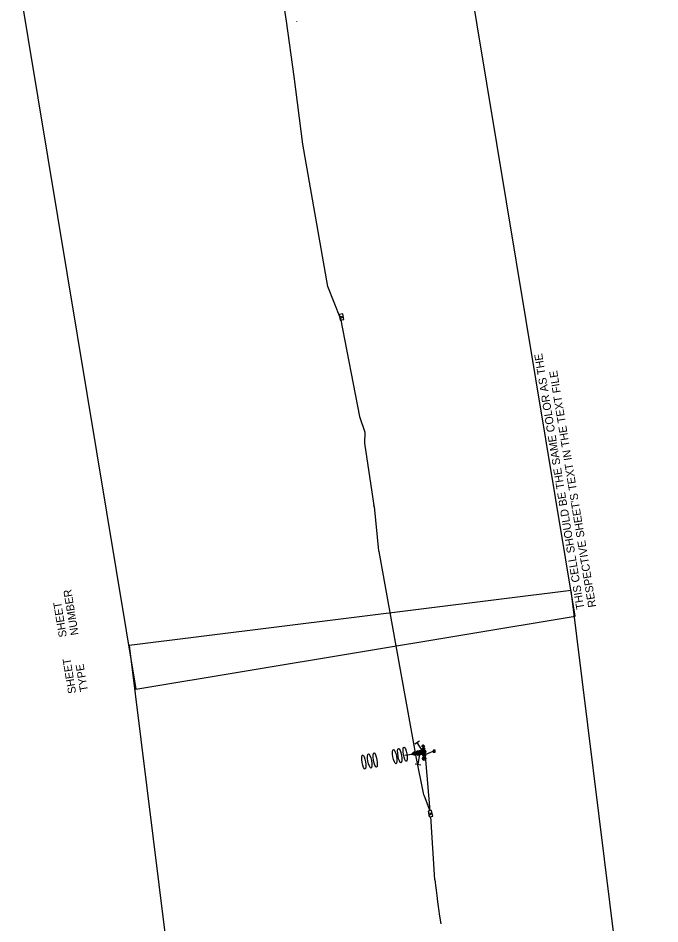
# Model space of a CAD drawing. Extents: x 601462 to 605493, y 331960 to 402715.
# Drawn here: x 603985 to 605389, y 335860 to 337841 of the extents above; entities that cross this region are included whole.
import ezdxf

# ---------------------------------------------------------------- set-up
doc = ezdxf.new("R2010")
doc.units = 0
for name, color, linetype in [('P_FTMS', 7, 'Continuous'), ('P_FTMSConduit', 7, 'Continuous'), ('P_MISC_TXT_2A (Construction)', 7, 'Continuous'), ('P_MISC_TXT_2B (Construction)', 7, 'Continuous')]:
    doc.layers.add(name, color=color, linetype=linetype)

# ---------------------------------------------------------------- blocks, each defined once
blk = doc.blocks.new('FTMS_FCV')
at = {"layer": 'P_FTMS'}
blk.add_line((13, 16), (1, -22), dxfattribs=at)
blk.add_lwpolyline([(39, 24), (-39, 24), (-39, -24), (39, -24)], close=True, dxfattribs=at)
blk.add_lwpolyline([(-12, 16), (1, -22)], dxfattribs=at)
blk = doc.blocks.new('FMD')
at = {"layer": 'P_FTMS'}
for p, q in [((17, 18), (-17, 18)), ((-16, 16), (-16, 18)), ((16, 16), (-16, 16)), ((-15, 15), (-15, 20)), ((15, 19), (-15, 19)), ((15, 15), (-15, 15)), ((14, 20), (-14, 20)), ((13, 22), (-13, 22)), ((-13, 13), (-13, 21)), ((13, 13), (-13, 13)), ((-12, 12), (-12, 23)), ((12, 12), (-12, 12)), ((11, 23), (-11, 23)), ((10, 25), (-10, 25)), ((-10, 10), (-10, 24)), ((10, 10), (-10, 10)), ((-9, 9), (-9, 26)), ((9, 9), (-9, 9)), ((8, 26), (-8, 26)), ((7, 28), (-7, 28)), ((-7, 7), (-7, 27)), ((7, 7), (-7, 7)), ((-6, 6), (-6, 29)), ((6, 6), (-6, 6)), ((5, 29), (-5, 29)), ((4, 31), (-4, 31)), ((-4, 4), (-4, 30)), ((4, 4), (-4, 4)), ((-3, 3), (-3, 32)), ((3, 3), (-3, 3)), ((2, 32), (-2, 32)), ((1, 34), (-1, 34)), ((-1, 1), (-1, 33)), ((1, 1), (-1, 1)), ((0, 0), (0, 34)), ((1, 1), (1, 33)), ((3, 3), (3, 32)), ((4, 4), (4, 30)), ((6, 6), (6, 29)), ((7, 7), (7, 27)), ((9, 9), (9, 26)), ((10, 10), (10, 24)), ((12, 12), (12, 23)), ((13, 13), (13, 21)), ((15, 15), (15, 20)), ((16, 16), (16, 18))]:
    blk.add_line(p, q, dxfattribs=at)
blk.add_lwpolyline([(-17, 17), (0, 34), (17, 17), (0, 0)], close=True, dxfattribs=at)
blk = doc.blocks.new('FMB')
at = {"layer": 'P_FTMS'}
for p, q in [((24, -24), (-24, 24)), ((-24, -24), (24, 24))]:
    blk.add_line(p, q, dxfattribs=at)
blk.add_lwpolyline([(24, -24), (24, 24), (-24, 24), (-24, -24)], close=True, dxfattribs=at)
blk = doc.blocks.new('_U256')
at = {"layer": 'P_FTMS'}
for points in [[(-15, -7), (7, -15), (0, 0)], [(15, 7), (-7, 15), (0, 0)]]:
    blk.add_lwpolyline(points, close=True, dxfattribs=at)
at = {"layer": 'P_FTMS', "xscale": 0.4713263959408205, "yscale": 0.4713263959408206, "rotation": 70.39802054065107}
blk.add_blockref('FMB', (0, 0), dxfattribs=at)
blk = doc.blocks.new('FTMS')
at = {"layer": 'P_FTMS'}
for p, q in [((-23, 0), (26, 0)), ((0, 24), (0, -24))]:
    blk.add_line(p, q, dxfattribs=at)
blk.add_lwpolyline([(26, -24), (26, 24), (-23, 24), (-23, -24)], close=True, dxfattribs=at)
blk = doc.blocks.new('FTMS_FERA')
at = {"layer": 'P_FTMS'}
for p, q in [((-65, 37), (-65, -37)), ((65, 0), (-65, 0))]:
    blk.add_line(p, q, dxfattribs=at)

msp = doc.modelspace()

# ---------------------------------------------------------------- linework, layer by layer
at = {"layer": 'P_FTMS'}
for p, q in [((604868.9, 336236), (604871.8, 336240)), ((604868.9, 336236.3), (604871.4, 336239.9)), ((604869, 336235.3), (604872.5, 336240.1)), ((604869, 336235.6), (604872.2, 336240.1)), ((604869.1, 336235), (604872.8, 336240.2)), ((604869.2, 336234.7), (604873.1, 336240.2)), ((604869.3, 336234.4), (604873.4, 336240.1)), ((604869.5, 336234.2), (604873.6, 336240.1)), ((604869.6, 336234), (604873.9, 336240)), ((604869.7, 336233.8), (604874.1, 336240)), ((604869.9, 336233.6), (604874.4, 336239.9)), ((604876.9, 336236), (604871.4, 336239.9)), ((604876.9, 336236.3), (604871.7, 336240)), ((604876.9, 336236.6), (604872, 336240.1)), ((604876.8, 336236.9), (604872.3, 336240.1)), ((604876.7, 336237.3), (604872.7, 336240.2)), ((604876.6, 336237.7), (604873.1, 336240.2)), ((604876.4, 336238.1), (604873.6, 336240.1)), ((604876, 336238.7), (604874.2, 336240)), ((604831.4, 336229), (604846.4, 336231.6)), ((604846.4, 336231.6), (604846.4, 336231.6)), ((604846.6, 336231.5), (604847.1, 336232.2)), ((604847.3, 336231.3), (604846.6, 336231.8)), ((604848.2, 336231), (604846.8, 336231.9)), ((604846.9, 336231.4), (604847.8, 336232.8)), ((604849, 336230.6), (604847, 336232.1)), ((604847.1, 336231.4), (604848.6, 336233.4)), ((604849.9, 336230.3), (604847.2, 336232.3)), ((604847.3, 336231.3), (604849.3, 336234)), ((604850.8, 336230), (604847.4, 336232.4)), ((604847.6, 336231.2), (604850, 336234.6)), ((604851.6, 336229.7), (604847.6, 336232.6)), ((604847.8, 336231.1), (604850.7, 336235.2)), ((604852.5, 336229.4), (604847.8, 336232.7)), ((604853.4, 336229), (604847.9, 336232.9)), ((604848, 336231), (604851.4, 336235.8)), ((604853.9, 336229), (604848.1, 336233)), ((604848.3, 336230.9), (604852.1, 336236.4)), ((604853.8, 336229.3), (604848.3, 336233.2)), ((604848.5, 336230.8), (604852.6, 336236.6)), ((604853.7, 336229.7), (604848.5, 336233.4)), ((604848.7, 336230.8), (604852.6, 336236.2)), ((604853.7, 336230), (604848.7, 336233.5)), ((604853.6, 336230.3), (604848.9, 336233.7)), ((604849, 336230.7), (604852.7, 336235.9)), ((604853.6, 336230.7), (604849.1, 336233.8)), ((604849.2, 336230.6), (604852.7, 336235.6)), ((604853.5, 336231), (604849.3, 336234)), ((604849.4, 336230.5), (604852.8, 336235.2)), ((604853.5, 336231.3), (604849.5, 336234.2)), ((604849.7, 336230.4), (604852.8, 336234.9)), ((604853.4, 336231.7), (604849.7, 336234.3)), ((604849.9, 336230.3), (604852.9, 336234.6)), ((604853.3, 336232), (604849.9, 336234.5)), ((604853.3, 336232.3), (604850, 336234.6)), ((604850.1, 336230.2), (604853, 336234.2)), ((604853.2, 336232.7), (604850.2, 336234.8)), ((604853.2, 336233), (604850.4, 336235)), ((604850.4, 336230.2), (604853, 336233.9)), ((604853.1, 336233.3), (604850.6, 336235.1)), ((604850.6, 336230.1), (604853.1, 336233.6)), ((604853.1, 336233.7), (604850.8, 336235.3)), ((604850.8, 336230), (604853.1, 336233.2)), ((604853, 336234), (604851, 336235.4)), ((604851.1, 336229.9), (604853.2, 336232.9)), ((604852.9, 336234.3), (604851.2, 336235.6)), ((604851.3, 336229.8), (604853.2, 336232.5)), ((604852.9, 336234.7), (604851.4, 336235.7)), ((604851.5, 336229.7), (604853.3, 336232.2)), ((604852.8, 336235), (604851.6, 336235.9)), ((604852.8, 336235.4), (604851.8, 336236.1)), ((604851.8, 336229.6), (604853.4, 336231.9)), ((604852.7, 336235.7), (604852, 336236.2)), ((604852, 336229.5), (604853.4, 336231.5)), ((604852.7, 336236), (604852.1, 336236.4)), ((604852.2, 336229.5), (604853.5, 336231.2)), ((604852.6, 336236.4), (604852.3, 336236.5)), ((604852.5, 336236.7), (604852.5, 336236.7)), ((604852.5, 336229.4), (604853.5, 336230.9)), ((604852.7, 336229.3), (604853.6, 336230.5)), ((604852.9, 336229.2), (604853.7, 336230.2)), ((604857.1, 336233.5), (604853.2, 336232.8)), ((604853.2, 336229.1), (604853.7, 336229.9)), ((604853.4, 336229), (604853.8, 336229.5)), ((604853.6, 336228.9), (604853.8, 336229.2)), ((604853.9, 336228.9), (604853.9, 336228.9)), ((604856.5, 336237.2), (604856.7, 336237.4)), ((604865.5, 336230.9), (604856.5, 336237.2)), ((604856.6, 336236.6), (604857.3, 336237.6)), ((604856.6, 336236.9), (604857, 336237.5)), ((604865.9, 336230.9), (604856.6, 336237.4)), ((604865.2, 336230.8), (604856.6, 336236.9)), ((604864.8, 336230.7), (604856.6, 336236.6)), ((604856.7, 336235.9), (604858, 336237.7)), ((604856.7, 336236.2), (604857.7, 336237.6)), ((604864.5, 336230.7), (604856.7, 336236.2)), ((604864.2, 336230.6), (604856.7, 336235.9)), ((604856.8, 336235.2), (604858.7, 336237.8)), ((604856.8, 336235.6), (604858.3, 336237.7)), ((604863.8, 336230.6), (604856.8, 336235.6)), ((604863.5, 336230.5), (604856.8, 336235.2)), ((604856.9, 336234.9), (604859, 336237.9)), ((604863.2, 336230.4), (604856.9, 336234.9)), ((604857, 336234.2), (604859.7, 336238)), ((604857, 336234.5), (604859.3, 336237.9)), ((604866.2, 336231), (604857, 336237.5)), ((604862.8, 336230.4), (604857, 336234.5)), ((604862.5, 336230.3), (604857, 336234.2)), ((604857.1, 336233.5), (604860.3, 336238.1)), ((604857.1, 336233.9), (604860, 336238)), ((604862.2, 336230.3), (604857.1, 336233.9)), ((604861.8, 336230.2), (604857.1, 336233.5)), ((604857.2, 336233.2), (604860.7, 336238.1)), ((604861.5, 336230.2), (604857.2, 336233.2)), ((604857.3, 336232.5), (604861.3, 336238.3)), ((604857.3, 336232.9), (604861, 336238.2)), ((604866.5, 336231), (604857.3, 336237.6)), ((604861.2, 336230.1), (604857.3, 336232.9)), ((604860.8, 336230), (604857.3, 336232.5)), ((604857.4, 336231.9), (604862, 336238.4)), ((604857.4, 336232.2), (604861.7, 336238.3)), ((604860.5, 336230), (604857.4, 336232.2)), ((604860.2, 336229.9), (604857.4, 336231.9)), ((604857.5, 336231.2), (604862.7, 336238.5)), ((604857.5, 336231.5), (604862.4, 336238.4)), ((604859.8, 336229.9), (604857.5, 336231.5)), ((604859.5, 336229.8), (604857.5, 336231.2)), ((604857.6, 336230.9), (604863, 336238.5)), ((604866.9, 336231.1), (604857.6, 336237.6)), ((604859.2, 336229.8), (604857.6, 336230.9)), ((604857.7, 336230.2), (604863.7, 336238.7)), ((604857.7, 336230.5), (604863.4, 336238.6)), ((604858.8, 336229.7), (604857.7, 336230.5)), ((604858.5, 336229.6), (604857.7, 336230.2)), ((604857.8, 336229.5), (604864.4, 336238.8)), ((604857.8, 336229.9), (604864, 336238.7)), ((604858.2, 336229.6), (604857.8, 336229.9)), ((604867.2, 336231.1), (604858, 336237.7)), ((604858.2, 336229.6), (604864.7, 336238.8)), ((604867.5, 336231.2), (604858.3, 336237.7)), ((604858.5, 336229.6), (604865, 336238.9)), ((604867.9, 336231.3), (604858.6, 336237.8)), ((604858.8, 336229.7), (604865.4, 336238.9)), ((604868.2, 336231.3), (604859, 336237.8)), ((604859.2, 336229.8), (604865.7, 336239)), ((604868.5, 336231.4), (604859.3, 336237.9)), ((604859.5, 336229.8), (604866, 336239.1)), ((604868.9, 336231.4), (604859.6, 336238)), ((604859.8, 336229.9), (604866.4, 336239.1)), ((604869.2, 336231.5), (604860, 336238)), ((604860.2, 336229.9), (604866.7, 336239.2)), ((604869.5, 336231.5), (604860.3, 336238.1)), ((604860.5, 336230), (604867, 336239.2)), ((604869.6, 336231.8), (604860.6, 336238.1)), ((604860.8, 336230), (604867.4, 336239.3)), ((604869.6, 336232.1), (604861, 336238.2)), ((604861.2, 336230.1), (604867.7, 336239.3)), ((604869.5, 336232.4), (604861.3, 336238.2)), ((604861.5, 336230.2), (604868, 336239.4)), ((604869.4, 336232.8), (604861.6, 336238.3)), ((604861.8, 336230.2), (604868.3, 336239.4)), ((604869.4, 336233.1), (604862, 336238.4)), ((604862.2, 336230.3), (604868.4, 336239)), ((604869.3, 336233.4), (604862.3, 336238.4)), ((604862.5, 336230.3), (604868.4, 336238.7)), ((604869.3, 336233.8), (604862.6, 336238.5)), ((604862.8, 336230.4), (604868.5, 336238.4)), ((604869.2, 336234.1), (604863, 336238.5)), ((604863.2, 336230.4), (604868.5, 336238)), ((604869.2, 336234.5), (604863.3, 336238.6)), ((604863.5, 336230.5), (604868.6, 336237.7)), ((604869.1, 336234.8), (604863.6, 336238.6)), ((604863.8, 336230.6), (604868.7, 336237.4)), ((604869, 336235.1), (604864, 336238.7)), ((604864.2, 336230.6), (604868.7, 336237)), ((604869, 336235.5), (604864.3, 336238.8)), ((604864.3, 336234.7), (604864.5, 336234.7)), ((604864.3, 336234.7), (604864.3, 336234.7)), ((604864.5, 336230.7), (604868.8, 336236.7)), ((604868.9, 336235.8), (604864.6, 336238.8)), ((604864.8, 336230.7), (604868.8, 336236.4)), ((604868.9, 336236.1), (604865, 336238.9)), ((604865.2, 336230.8), (604868.9, 336236)), ((604868.8, 336236.5), (604865.3, 336238.9)), ((604865.5, 336230.9), (604868.9, 336235.7)), ((604868.8, 336236.8), (604865.6, 336239)), ((604865.9, 336230.9), (604869, 336235.4)), ((604868.7, 336237.1), (604866, 336239)), ((604866.2, 336231), (604869.1, 336235)), ((604868.6, 336237.5), (604866.3, 336239.1)), ((604866.5, 336231), (604869.1, 336234.7)), ((604868.6, 336237.8), (604866.7, 336239.2)), ((604866.9, 336231.1), (604869.2, 336234.4)), ((604868.5, 336238.1), (604867, 336239.2)), ((604867.2, 336231.1), (604869.2, 336234)), ((604868.5, 336238.5), (604867.3, 336239.3)), ((604867.5, 336231.2), (604869.3, 336233.7)), ((604868.4, 336238.8), (604867.7, 336239.3)), ((604867.9, 336231.3), (604869.3, 336233.4)), ((604868.4, 336239.1), (604868, 336239.4)), ((604868.2, 336231.3), (604869.4, 336233)), ((604868.5, 336231.4), (604869.5, 336232.7)), ((604874.4, 336232.5), (604868.9, 336236.4)), ((604874.1, 336232.4), (604868.9, 336236.1)), ((604873.8, 336232.3), (604868.9, 336235.8)), ((604868.9, 336231.4), (604869.5, 336232.3)), ((604869, 336236.9), (604871, 336239.7)), ((604875.1, 336232.8), (604869, 336237.2)), ((604874.9, 336232.7), (604869, 336236.9)), ((604874.7, 336232.6), (604869, 336236.6)), ((604873.5, 336232.2), (604869, 336235.4)), ((604875.3, 336233), (604869.1, 336237.4)), ((604873.2, 336232.2), (604869.1, 336235.1)), ((604869.2, 336237.5), (604870.4, 336239.3)), ((604875.5, 336233.2), (604869.2, 336237.6)), ((604872.7, 336232.2), (604869.2, 336234.7)), ((604869.2, 336231.5), (604869.6, 336232)), ((604875.7, 336233.3), (604869.3, 336237.9)), ((604875.9, 336233.5), (604869.4, 336238.1)), ((604872.2, 336232.3), (604869.4, 336234.2)), ((604876, 336233.7), (604869.5, 336238.3)), ((604869.5, 336231.5), (604869.6, 336231.7)), ((604876.2, 336233.9), (604869.7, 336238.5)), ((604876.3, 336234.1), (604869.8, 336238.7)), ((604871.6, 336232.4), (604869.8, 336233.7)), ((604876.4, 336234.3), (604870, 336238.9)), ((604870.1, 336233.4), (604874.6, 336239.8)), ((604876.5, 336234.5), (604870.1, 336239)), ((604870.2, 336233.2), (604874.8, 336239.7)), ((604876.6, 336234.7), (604870.3, 336239.2)), ((604870.4, 336233.1), (604875, 336239.6)), ((604876.7, 336235), (604870.5, 336239.4)), ((604870.6, 336232.9), (604875.2, 336239.4)), ((604876.8, 336235.2), (604870.7, 336239.5)), ((604870.8, 336232.8), (604875.4, 336239.3)), ((604876.8, 336235.5), (604870.9, 336239.6)), ((604871, 336232.7), (604875.6, 336239.1)), ((604876.9, 336235.7), (604871.2, 336239.8)), ((604871.2, 336232.6), (604875.8, 336239)), ((604871.5, 336232.5), (604875.9, 336238.8)), ((604871.7, 336232.4), (604876.1, 336238.6)), ((604871.9, 336232.3), (604876.2, 336238.4)), ((604872.2, 336232.3), (604876.4, 336238.2)), ((604872.5, 336232.2), (604876.5, 336237.9)), ((604872.7, 336232.2), (604876.6, 336237.7)), ((604873, 336232.2), (604876.7, 336237.4)), ((604873.3, 336232.2), (604876.8, 336237.1)), ((604873.7, 336232.3), (604876.9, 336236.8)), ((604874, 336232.3), (604876.9, 336236.4)), ((604874.4, 336232.5), (604876.9, 336236)), ((604874.9, 336232.7), (604876.9, 336235.5)), ((604875.4, 336233.1), (604876.7, 336234.8))]:
    msp.add_line(p, q, dxfattribs=at)
for points in [[(604853.9, 336228.9), (604852.5, 336236.7), (604846.4, 336231.6)], [(604868.3, 336239.4), (604856.5, 336237.4), (604857.8, 336229.5), (604869.7, 336231.6)]]:
    msp.add_lwpolyline(points, close=True, dxfattribs=at)
for centre, radius in [((604872.9, 336236.2), 4), ((604873.4, 336221.6), 3.75)]:
    msp.add_circle(centre, radius, dxfattribs=at)
for centre, start, end in [((604873.5, 336226.1), 216.2095, 322.4651), ((604873.4, 336217.1), 36.2095, 142.4651)]:
    msp.add_arc(centre, 3.75, start, end, dxfattribs=at)
for centre in [(604808.8, 336226.1), (604819.9, 336228), (604831.7, 336231.2), (604741.4, 336214), (604754.1, 336216.6), (604766.3, 336218.7)]:
    msp.add_ellipse(centre, major_axis=(-2.7, 15.7), ratio=0.23471, dxfattribs=at)
at = {"layer": 'P_FTMSConduit'}
for p, q in [((604571.9, 337834.4), (604551.5, 337974.3)), ((604662.5, 337254.2), (604607.7, 337565.9)), ((604690.3, 337184), (604662.5, 337254.2)), ((604876.4, 336223.8), (604877.1, 336229.9)), ((604877.7, 336231.2), (604893.2, 336237.8)), ((604876.4, 336219.3), (604885.8, 336107.7)), ((604896.8, 335956.8), (604888.3, 336095.2))]:
    msp.add_line(p, q, dxfattribs=at)
for points in [[(604607.7, 337565.9), (604588.8, 337713.8), (604571.9, 337834.4)], [(604690.3, 337184), (604731.6, 336969.7), (604743.6, 336935.5), (604743, 336911.3), (604763.4, 336775)], [(604763.7, 336773.2), (604773.7, 336676.4)], [(604774, 336674.5), (604811.2, 336468)], [(604811.2, 336468), (604855.1, 336226.4)], [(604855.2, 336225.9), (604871.3, 336146.1)], [(604870.1, 336233.3), (604869.7, 336232.1)], [(604870.3, 336228), (604872, 336225.1)], [(604873.2, 336140.4), (604885.8, 336107.7)]]:
    msp.add_lwpolyline(points, dxfattribs=at)
for centre, radius, start, end in [((604618.9, 337836.9), 25, 185.9108, 187.9759), ((604738.8, 336770.6), 25, 5.9259, 10.1494), ((604798.6, 336679), 25, 185.9259, 190.207), ((604835.8, 336472.4), 25, 190.207, 190.3136), ((604879.7, 336230.9), 25, 190.3136, 191.3801), ((604874.5, 336230.7), 5, 163.7872, 212.7361), ((604895.8, 336151.1), 25, 191.3801, 205.343)]:
    msp.add_arc(centre, radius, start, end, dxfattribs=at)
msp.add_ellipse((604911.6, 335860.4), major_axis=(14.7, -98.9), ratio=0.01969, start_param=3.365032, end_param=4.712389, dxfattribs=at)
at = {"layer": 'P_MISC_TXT_2A (Construction)'}
msp.add_lwpolyline([(605389.3, 335026.4), (605195.3, 336589.4), (604227.7, 336469.3), (604421.8, 334906.3)], close=True, dxfattribs=at)
at = {"layer": 'P_MISC_TXT_2B (Construction)'}
msp.add_lwpolyline([(605203.9, 336533.1), (604946.5, 338086.9), (603984.6, 337927.6), (604242.1, 336373.7)], close=True, dxfattribs=at)

# ---------------------------------------------------------------- block references
at = {"layer": 'P_FTMS'}
for name, p, xscale, yscale, rotation in [('FTMS_FCV', (604692.5, 337187.5), 0.16404166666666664, 0.1640416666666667, 100.29615606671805), ('FTMS_FERA', (604863.8, 336247.8), 0.16404166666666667, 0.16404166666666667, -56.08017900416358), ('FMD', (604873.9, 336249.1), 0.16404166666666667, 0.16404166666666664, 99.31845373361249), ('FMD', (604874.8, 336243.6), 0.16404166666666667, 0.16404166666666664, 99.31845373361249), ('FTMS_FERA', (604861.5, 336219.8), 0.16404166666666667, 0.16404166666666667, 80.52441712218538), ('_U256', (604874, 336230), 0.19684999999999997, 0.19684999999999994, -149.66649616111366), ('FTMS_FCV', (604887.1, 336101.4), 0.16404166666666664, 0.16404166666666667, 101.34714958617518)]:
    msp.add_blockref(name, p, dxfattribs=dict(at, xscale=xscale, yscale=yscale, rotation=rotation))
at = {"layer": 'P_FTMS', "xscale": 0.08202083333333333, "yscale": 0.08202083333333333}
msp.add_blockref('FTMS', (604895.1, 336237.8), dxfattribs=at)

# ---------------------------------------------------------------- texts
at = {"layer": 'P_MISC_TXT_2B (Construction)'}
for s, p in [('THIS CELL SHOULD BE THE SAME COLOR AS THE', (605224.1, 336549.6)), ("RESPECTIVE SHEET'S TEXT IN THE TEXT FILE", (605250, 336553.9)), ('NUMBER', (604117.3, 336492.9)), ('SHEET', (604091.4, 336488.6)), ('SHEET', (604111.8, 336365.3)), ('TYPE', (604137.7, 336369.6))]:
    msp.add_text(s, height=17.5, rotation=99.4069, dxfattribs=at).set_placement(p)

doc.saveas('drawing.dxf')
